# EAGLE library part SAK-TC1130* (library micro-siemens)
32-Bit Industrial &Communication Controller Source: http://www.infineon.com .. TC1130_DS_v031.pdf
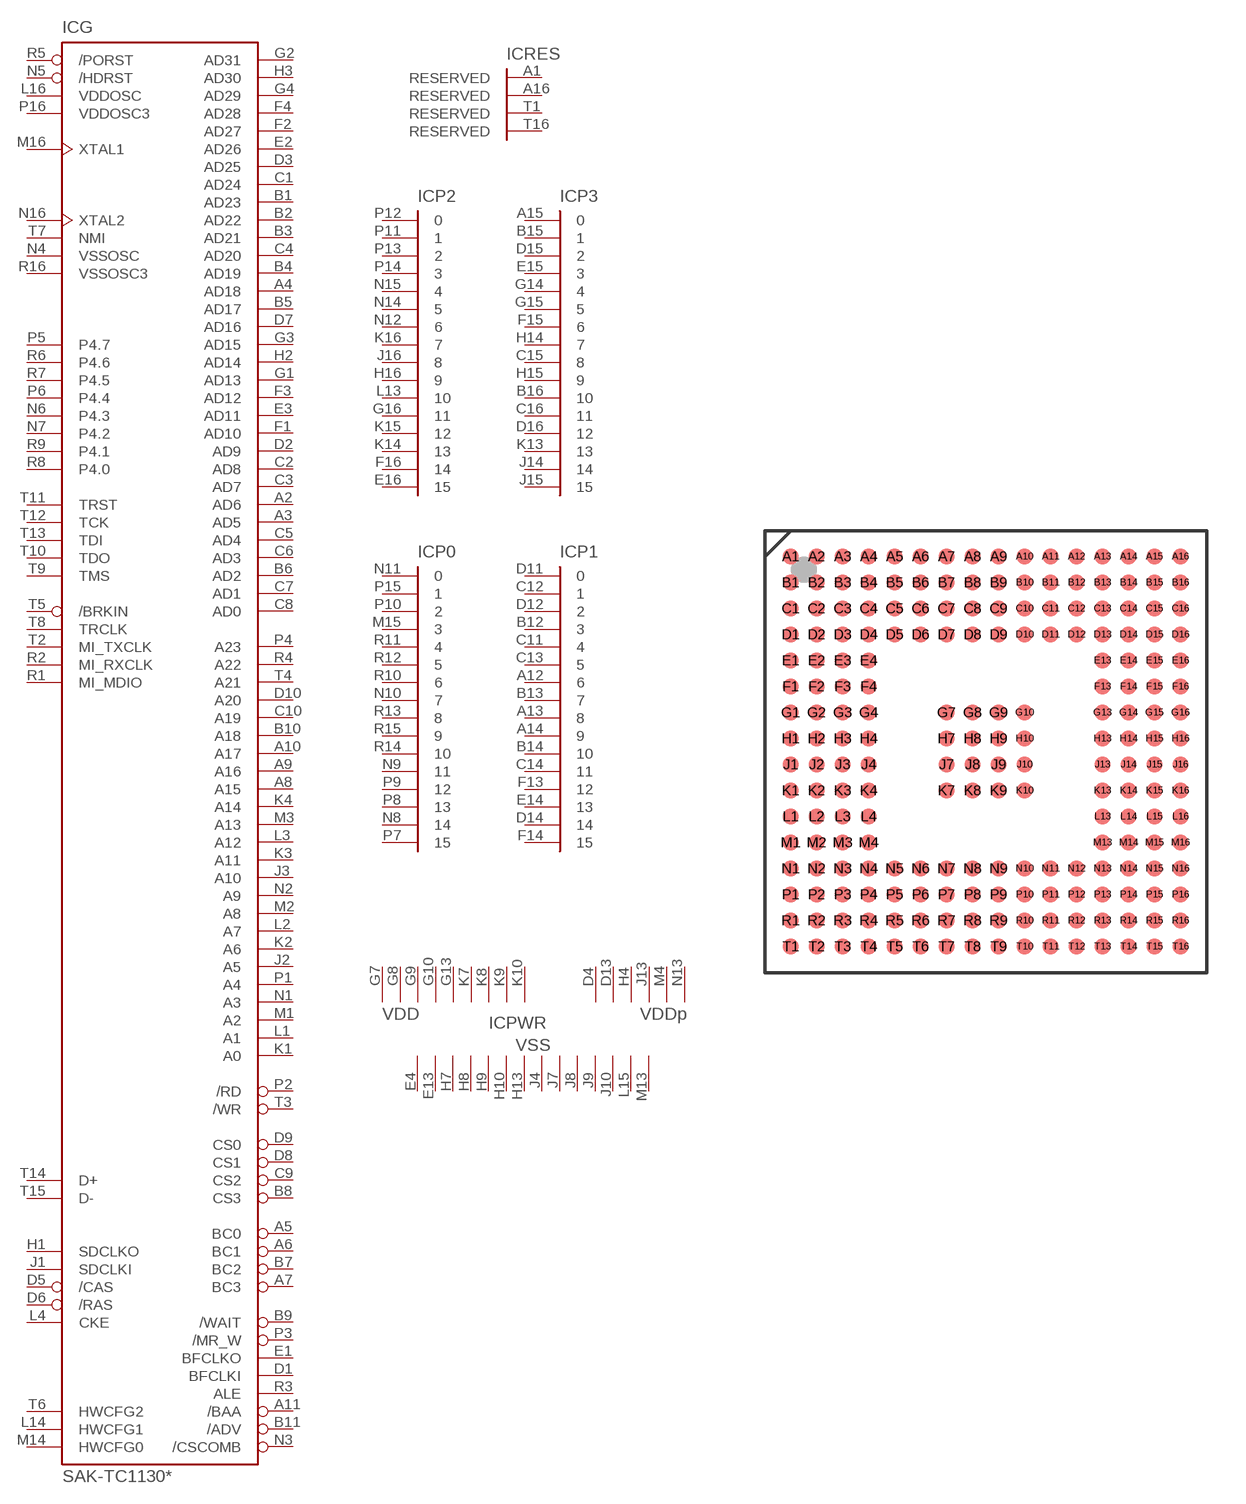
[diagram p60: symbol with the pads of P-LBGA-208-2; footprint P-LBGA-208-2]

Designator prefix IC; gates G=TC1130 PWR=PWR_TC1130 P0=PORT16 P1=PORT16 P2=PORT16 P3=PORT16 RES=NC4

## SAK-TC1130 (OC_FARNELL: unknown; OC_NEWARK: unknown)  [P-LBGA-208-2]
A1  RES:RESERVED  nc
A2  G:AD6
A3  G:AD5
A4  G:AD18
A5  G:BC0
A6  G:BC1
A7  G:BC3
A8  G:A15
A9  G:A16
A10  G:A17
A11  G:/BAA
A12  P1:6  in
A13  P1:8  in
A14  P1:9  in
A15  P3:0  in
A16  RES:RESERVED  nc
B1  G:AD23
B2  G:AD22
B3  G:AD21
B4  G:AD19
B5  G:AD17
B6  G:AD2
B7  G:BC2
B8  G:CS3
B9  G:/WAIT
B10  G:A18
B11  G:/ADV
B12  P1:3  in
B13  P1:7  in
B14  P1:10  in
B15  P3:1  in
B16  P3:10  in
C1  G:AD24
C2  G:AD8
C3  G:AD7
C4  G:AD20
C5  G:AD4
C6  G:AD3
C7  G:AD1
C8  G:AD0
C9  G:CS2
C10  G:A19
C11  P1:4  in
C12  P1:1  in
C13  P1:5  in
C14  P1:11  in
C15  P3:8  in
C16  P3:11  in
D1  G:BFCLKI
D2  G:AD9
D3  G:AD25
D4  PWR:VDDP  pwr
D5  G:/CAS
D6  G:/RAS
D7  G:AD16
D8  G:CS1
D9  G:CS0
D10  G:A20
D11  P1:0  in
D12  P1:2  in
D13  PWR:VDDP  pwr
D14  P1:14  in
D15  P3:2  in
D16  P3:12  in
E1  G:BFCLKO
E2  G:AD26
E3  G:AD11
E4  PWR:VSS  pwr
E13  PWR:VSS  pwr
E14  P1:13  in
E15  P3:3  in
E16  P2:15  in
F1  G:AD10
F2  G:AD27
F3  G:AD12
F4  G:AD28
F13  P1:12  in
F14  P1:15  in
F15  P3:6  in
F16  P2:14  in
G1  G:AD13
G2  G:AD31
G3  G:AD15
G4  G:AD29
G7  PWR:VDD  pwr
G8  PWR:VDD  pwr
G9  PWR:VDD  pwr
G10  PWR:VDD  pwr
G13  PWR:VDD  pwr
G14  P3:4  in
G15  P3:5  in
G16  P2:11  in
H1  G:SDCLKO
H2  G:AD14
H3  G:AD30
H4  PWR:VDDP  pwr
H7  PWR:VSS  pwr
H8  PWR:VSS  pwr
H9  PWR:VSS  pwr
H10  PWR:VSS  pwr
H13  PWR:VSS  pwr
H14  P3:7  in
H15  P3:9  in
H16  P2:9  in
J1  G:SDCLKI
J2  G:A5
J3  G:A10
J4  PWR:VSS  pwr
J7  PWR:VSS  pwr
J8  PWR:VSS  pwr
J9  PWR:VSS  pwr
J10  PWR:VSS  pwr
J13  PWR:VDDP  pwr
J14  P3:14  in
J15  P3:15  in
J16  P2:8  in
K1  G:A0
K2  G:A6
K3  G:A11
K4  G:A14
K7  PWR:VDD  pwr
K8  PWR:VDD  pwr
K9  PWR:VDD  pwr
K10  PWR:VDD  pwr
K13  P3:13  in
K14  P2:13  in
K15  P2:12  in
K16  P2:7  in
L1  G:A1
L2  G:A7
L3  G:A12
L4  G:CKE
L13  P2:10  in
L14  G:HWCFG1
L15  PWR:VSS  pwr
L16  G:VDDOSC
M1  G:A2
M2  G:A8
M3  G:A13
M4  PWR:VDDP  pwr
M13  PWR:VSS  pwr
M14  G:HWCFG0
M15  P0:3  in
M16  G:XTAL1
N1  G:A3
N2  G:A9
N3  G:/CSCOMB
N4  G:VSSOSC
N5  G:/HDRST
N6  G:P4.3
N7  G:P4.2
N8  P0:14  in
N9  P0:11  in
N10  P0:7  in
N11  P0:0  in
N12  P2:6  in
N13  PWR:VDDP  pwr
N14  P2:5  in
N15  P2:4  in
N16  G:XTAL2
P1  G:A4
P2  G:/RD
P3  G:/MR_W
P4  G:A23
P5  G:P4.7
P6  G:P4.4
P7  P0:15  in
P8  P0:13  in
P9  P0:12  in
P10  P0:2  in
P11  P2:1  in
P12  P2:0  in
P13  P2:2  in
P14  P2:3  in
P15  P0:1  in
P16  G:VDDOSC3
R1  G:MI_MDIO
R2  G:MI_RXCLK
R3  G:ALE
R4  G:A22
R5  G:/PORST
R6  G:P4.6
R7  G:P4.5
R8  G:P4.0
R9  G:P4.1
R10  P0:6  in
R11  P0:4  in
R12  P0:5  in
R13  P0:8  in
R14  P0:10  in
R15  P0:9  in
R16  G:VSSOSC3
T1  RES:RESERVED  nc
T2  G:MI_TXCLK
T3  G:/WR
T4  G:A21
T5  G:/BRKIN
T6  G:HWCFG2
T7  G:NMI
T8  G:TRCLK
T9  G:TMS
T10  G:TDO
T11  G:TRST
T12  G:TCK
T13  G:TDI
T14  G:D+
T15  G:D-
T16  RES:RESERVED  nc

## Footprint P-LBGA-208-2 (pad centres in mm)
P-LBGA-208-2 Low Profile Plastic Ball Grid Array Package Source: http://www.infineon.com .. TC1130_DS_v031.pdf
smd 0.6 x 0.6: A1 -7.5,7.5; A2 -6.5,7.5; A3 -5.5,7.5; A4 -4.5,7.5; A5 -3.5,7.5; A6 -2.5,7.5; A7 -1.5,7.5; A8 -0.5,7.5; A9 0.5,7.5; A10 1.5,7.5; A11 2.5,7.5; A12 3.5,7.5; A13 4.5,7.5; A14 5.5,7.5; A15 6.5,7.5; A16 7.5,7.5; B1 -7.5,6.5; B2 -6.5,6.5; B3 -5.5,6.5; B4 -4.5,6.5; B5 -3.5,6.5; B6 -2.5,6.5; B7 -1.5,6.5; B8 -0.5,6.5; B9 0.5,6.5; B10 1.5,6.5; B11 2.5,6.5; B12 3.5,6.5; B13 4.5,6.5; B14 5.5,6.5; B15 6.5,6.5; B16 7.5,6.5; C1 -7.5,5.5; C2 -6.5,5.5; C3 -5.5,5.5; C4 -4.5,5.5; C5 -3.5,5.5; C6 -2.5,5.5; C7 -1.5,5.5; C8 -0.5,5.5; C9 0.5,5.5; C10 1.5,5.5; C11 2.5,5.5; C12 3.5,5.5; C13 4.5,5.5; C14 5.5,5.5; C15 6.5,5.5; C16 7.5,5.5; D1 -7.5,4.5; D2 -6.5,4.5; D3 -5.5,4.5; D4 -4.5,4.5; D5 -3.5,4.5; D6 -2.5,4.5; D7 -1.5,4.5; D8 -0.5,4.5; D9 0.5,4.5; D10 1.5,4.5; D11 2.5,4.5; D12 3.5,4.5; D13 4.5,4.5; D14 5.5,4.5; D15 6.5,4.5; D16 7.5,4.5; E1 -7.5,3.5; E2 -6.5,3.5; E3 -5.5,3.5; E4 -4.5,3.5; E13 4.5,3.5; E14 5.5,3.5; E15 6.5,3.5; E16 7.5,3.5; F1 -7.5,2.5; F2 -6.5,2.5; F3 -5.5,2.5; F4 -4.5,2.5; F13 4.5,2.5; F14 5.5,2.5; F15 6.5,2.5; F16 7.5,2.5; G1 -7.5,1.5; G2 -6.5,1.5; G3 -5.5,1.5; G4 -4.5,1.5; G7 -1.5,1.5; G8 -0.5,1.5; G9 0.5,1.5; G10 1.5,1.5; G13 4.5,1.5; G14 5.5,1.5; G15 6.5,1.5; G16 7.5,1.5; H1 -7.5,0.5; H2 -6.5,0.5; H3 -5.5,0.5; H4 -4.5,0.5; H7 -1.5,0.5; H8 -0.5,0.5; H9 0.5,0.5; H10 1.5,0.5; H13 4.5,0.5; H14 5.5,0.5; H15 6.5,0.5; H16 7.5,0.5; J1 -7.5,-0.5; J2 -6.5,-0.5; J3 -5.5,-0.5; J4 -4.5,-0.5; J7 -1.5,-0.5; J8 -0.5,-0.5; J9 0.5,-0.5; J10 1.5,-0.5; J13 4.5,-0.5; J14 5.5,-0.5; J15 6.5,-0.5; J16 7.5,-0.5; K1 -7.5,-1.5; K2 -6.5,-1.5; K3 -5.5,-1.5; K4 -4.5,-1.5; K7 -1.5,-1.5; K8 -0.5,-1.5; K9 0.5,-1.5; K10 1.5,-1.5; K13 4.5,-1.5; K14 5.5,-1.5; K15 6.5,-1.5; K16 7.5,-1.5; L1 -7.5,-2.5; L2 -6.5,-2.5; L3 -5.5,-2.5; L4 -4.5,-2.5; L13 4.5,-2.5; L14 5.5,-2.5; L15 6.5,-2.5; L16 7.5,-2.5; M1 -7.5,-3.5; M2 -6.5,-3.5; M3 -5.5,-3.5; M4 -4.5,-3.5; M13 4.5,-3.5; M14 5.5,-3.5; M15 6.5,-3.5; M16 7.5,-3.5; N1 -7.5,-4.5; N2 -6.5,-4.5; N3 -5.5,-4.5; N4 -4.5,-4.5; N5 -3.5,-4.5; N6 -2.5,-4.5; N7 -1.5,-4.5; N8 -0.5,-4.5; N9 0.5,-4.5; N10 1.5,-4.5; N11 2.5,-4.5; N12 3.5,-4.5; N13 4.5,-4.5; N14 5.5,-4.5; N15 6.5,-4.5; N16 7.5,-4.5; P1 -7.5,-5.5; P2 -6.5,-5.5; P3 -5.5,-5.5; P4 -4.5,-5.5; P5 -3.5,-5.5; P6 -2.5,-5.5; P7 -1.5,-5.5; P8 -0.5,-5.5; P9 0.5,-5.5; P10 1.5,-5.5; P11 2.5,-5.5; P12 3.5,-5.5; P13 4.5,-5.5; P14 5.5,-5.5; P15 6.5,-5.5; P16 7.5,-5.5; R1 -7.5,-6.5; R2 -6.5,-6.5; R3 -5.5,-6.5; R4 -4.5,-6.5; R5 -3.5,-6.5; R6 -2.5,-6.5; R7 -1.5,-6.5; R8 -0.5,-6.5; R9 0.5,-6.5; R10 1.5,-6.5; R11 2.5,-6.5; R12 3.5,-6.5; R13 4.5,-6.5; R14 5.5,-6.5; R15 6.5,-6.5; R16 7.5,-6.5; T1 -7.5,-7.5; T2 -6.5,-7.5; T3 -5.5,-7.5; T4 -4.5,-7.5; T5 -3.5,-7.5; T6 -2.5,-7.5; T7 -1.5,-7.5; T8 -0.5,-7.5; T9 0.5,-7.5; T10 1.5,-7.5; T11 2.5,-7.5; T12 3.5,-7.5; T13 4.5,-7.5; T14 5.5,-7.5; T15 6.5,-7.5; T16 7.5,-7.5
